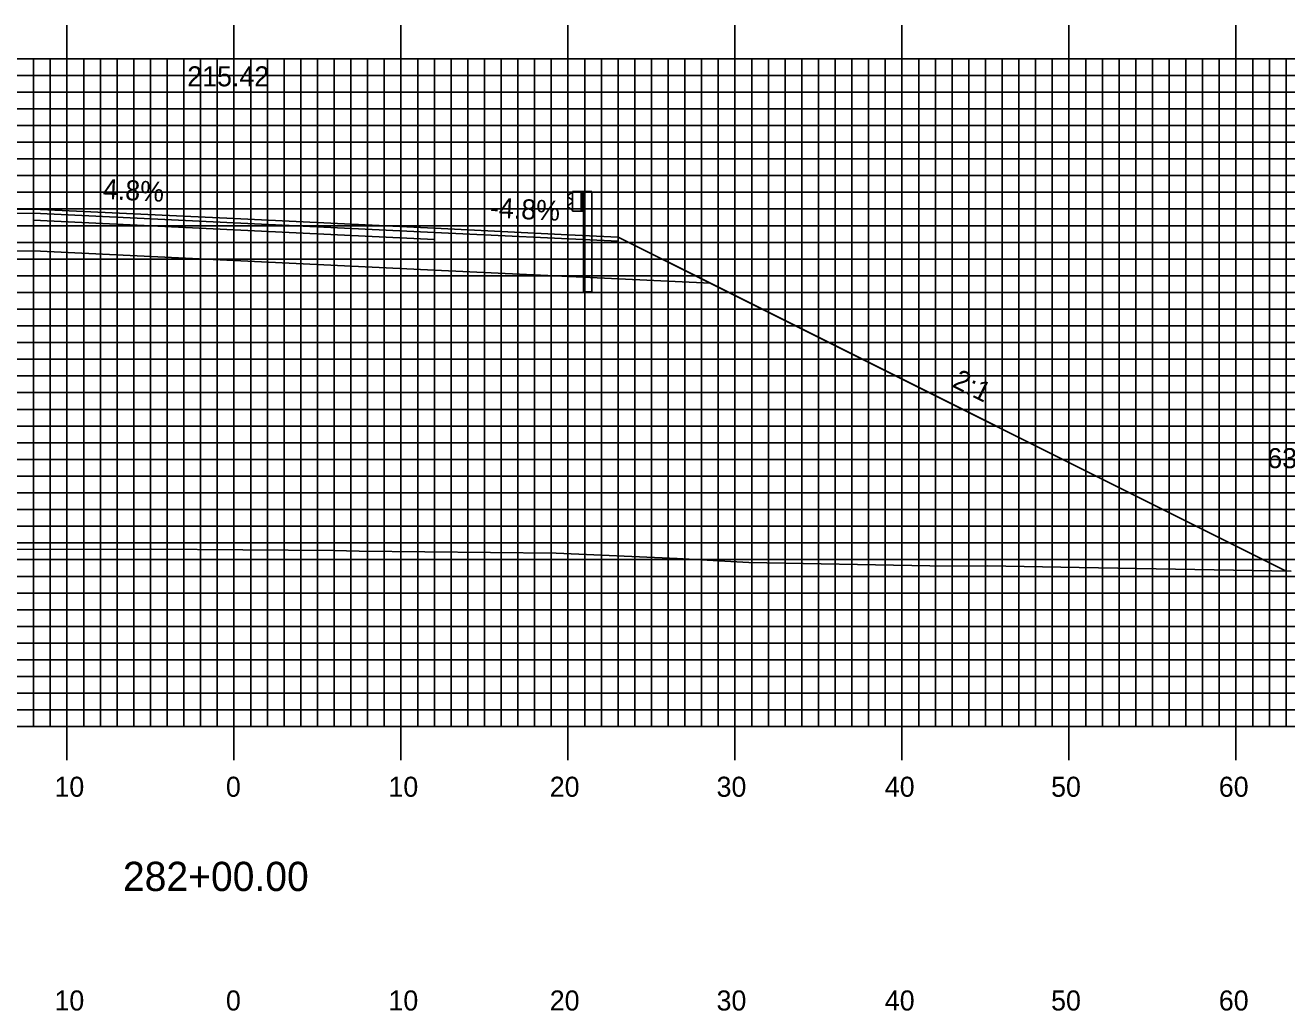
# Model space of a CAD drawing. Extents: x 1811374 to 1811717, y 442591 to 442811.
# Drawn here: x 1811526.9 to 1811602.4, y 442651.6 to 442710.7 of the extents above; entities that cross this region are included whole.
import ezdxf

# ---------------------------------------------------------------- set-up
doc = ezdxf.new("R2010")
doc.units = 0
for name, color, linetype in [('ANNOTATION', 7, 'Continuous'), ('D_Guardrail_Beam_Rt', 7, 'Continuous'), ('D_Roadway_Centerline', 7, 'Continuous'), ('D_Roadway_Centerline_Text', 7, 'Continuous'), ('D_Roadway_Edge_Shoulder', 7, 'Continuous'), ('D_Roadway_Edge_TW', 7, 'Continuous'), ('D_Roadway_Pavement', 7, 'Continuous'), ('D_Roadway_SlopeLines', 7, 'Continuous'), ('D_Roadway_SubGrade', 7, 'Continuous'), ('D_Text_Standard', 7, 'Continuous'), ('H_V ANNOTATION', 7, 'Continuous'), ('MAJOR', 7, 'Continuous'), ('MINOR', 7, 'Continuous'), ('S_Roadway_Centerline', 7, 'Continuous')]:
    doc.layers.add(name, color=color, linetype=linetype)

msp = doc.modelspace()

# ---------------------------------------------------------------- linework, layer by layer
at = {"layer": 'D_Guardrail_Beam_Rt'}
for p, q in [((1811559.674, 442700.709), (1811560.361, 442700.709)), ((1811559.674, 442699.543), (1811559.674, 442700.709)), ((1811560.194, 442700.709), (1811560.194, 442699.543)), ((1811560.299, 442700.709), (1811560.299, 442699.543)), ((1811560.361, 442700.709), (1811560.832, 442700.709)), ((1811560.361, 442700.709), (1811560.361, 442699.543)), ((1811560.832, 442700.709), (1811560.832, 442694.709)), ((1811559.584, 442700.605), (1811559.44, 442700.505)), ((1811559.44, 442700.362), (1811559.636, 442700.226)), ((1811559.636, 442700.027), (1811559.44, 442699.89)), ((1811559.674, 442700.626), (1811559.599, 442700.611)), ((1811559.669, 442700.161), (1811559.669, 442700.091)), ((1811559.44, 442699.747), (1811559.584, 442699.647)), ((1811559.599, 442699.641), (1811559.674, 442699.626)), ((1811560.361, 442699.543), (1811559.674, 442699.543)), ((1811560.34, 442694.709), (1811560.34, 442699.543)), ((1811560.34, 442694.709), (1811560.832, 442694.709))]:
    msp.add_line(p, q, dxfattribs=at)
for centre, major_axis, start_param, end_param in [((1811559.49, 442700.433), (-0.0877, 0), 5.323254, 7.243116), ((1811559.608, 442700.571), (-0.0417, 0), 4.907132, 5.323254), ((1811559.59, 442700.161), (0.0789, 0), 0, 0.959931), ((1811559.59, 442700.091), (0.0789, 0), 5.323254, 6.283185), ((1811559.49, 442699.819), (-0.0877, 0), 5.323254, 7.243116), ((1811559.608, 442699.681), (-0.0417, 0), 0.959931, 1.376053)]:
    msp.add_ellipse(centre, major_axis=major_axis, ratio=0.995501, start_param=start_param, end_param=end_param, dxfattribs=at)
at = {"layer": 'D_Roadway_Centerline'}
msp.add_lwpolyline([(1811475.943, 442679.212), (1811511.194, 442696.838), (1811516.403, 442699.442), (1811519.403, 442699.502), (1811527.403, 442699.662), (1811539.403, 442699.086), (1811551.403, 442698.51), (1811559.403, 442698.126), (1811562.403, 442697.982), (1811567.934, 442695.217), (1811602.417, 442677.975)], dxfattribs=at)
at = {"layer": 'D_Roadway_Edge_Shoulder'}
for points in [[(1811527.403, 442699.662), (1811519.403, 442699.502), (1811519.403, 442699.502), (1811516.403, 442699.442), (1811516.403, 442699.192), (1811527.403, 442699.412)], [(1811551.403, 442698.51), (1811559.403, 442698.126), (1811559.403, 442698.126), (1811562.403, 442697.982), (1811562.403, 442697.732), (1811551.403, 442698.26)]]:
    msp.add_lwpolyline(points, close=True, dxfattribs=at)
at = {"layer": 'D_Roadway_Edge_TW'}
msp.add_lwpolyline([(1811527.403, 442699.412), (1811527.403, 442699.662), (1811539.403, 442699.086), (1811551.403, 442698.51), (1811551.403, 442698.26), (1811539.403, 442698.836)], close=True, dxfattribs=at)
at = {"layer": 'D_Roadway_Pavement'}
msp.add_lwpolyline([(1811527.403, 442698.995), (1811527.403, 442699.412), (1811539.403, 442698.836), (1811551.403, 442698.26), (1811551.403, 442697.843), (1811539.403, 442698.419)], close=True, dxfattribs=at)
for points in [[(1811527.403, 442699.412), (1811527.403, 442698.995)], [(1811551.403, 442698.26), (1811551.403, 442697.843)]]:
    msp.add_lwpolyline(points, dxfattribs=at)
at = {"layer": 'D_Roadway_SlopeLines'}
msp.add_lwpolyline([(1811562.403, 442697.982), (1811602.417, 442677.975)], dxfattribs=at)
at = {"layer": 'D_Roadway_SubGrade'}
for points in [[(1811527.403, 442698.995), (1811527.403, 442699.412), (1811516.403, 442699.192), (1811516.403, 442699.442), (1811511.194, 442696.838), (1811527.403, 442697.162)], [(1811527.403, 442697.162), (1811527.403, 442699.412), (1811527.403, 442698.995), (1811539.403, 442698.419), (1811551.403, 442697.843), (1811551.403, 442698.26), (1811551.403, 442696.01), (1811539.403, 442696.586)], [(1811551.403, 442697.843), (1811551.403, 442698.26), (1811562.403, 442697.732), (1811562.403, 442697.982), (1811567.934, 442695.217), (1811551.403, 442696.01)]]:
    msp.add_lwpolyline(points, close=True, dxfattribs=at)
at = {"layer": 'MAJOR'}
for p, q in [((1811529.403, 442710.669), (1811529.403, 442708.665)), ((1811539.403, 442710.669), (1811539.403, 442708.665)), ((1811549.403, 442710.669), (1811549.403, 442708.665)), ((1811559.403, 442710.669), (1811559.403, 442708.665)), ((1811569.403, 442710.669), (1811569.403, 442708.665)), ((1811579.403, 442710.669), (1811579.403, 442708.665)), ((1811589.403, 442710.669), (1811589.403, 442708.665)), ((1811599.403, 442710.669), (1811599.403, 442708.665)), ((1811399.403, 442708.665), (1811679.403, 442708.665)), ((1811399.403, 442708.665), (1811679.403, 442708.665)), ((1811529.403, 442668.665), (1811529.403, 442708.665)), ((1811539.403, 442668.665), (1811539.403, 442708.665)), ((1811549.403, 442668.665), (1811549.403, 442708.665)), ((1811559.403, 442668.665), (1811559.403, 442708.665)), ((1811569.403, 442668.665), (1811569.403, 442708.665)), ((1811579.403, 442668.665), (1811579.403, 442708.665)), ((1811589.403, 442668.665), (1811589.403, 442708.665)), ((1811599.403, 442668.665), (1811599.403, 442708.665)), ((1811399.403, 442703.665), (1811679.403, 442703.665)), ((1811399.403, 442698.665), (1811679.403, 442698.665)), ((1811399.403, 442693.665), (1811679.403, 442693.665)), ((1811399.403, 442688.665), (1811679.403, 442688.665)), ((1811399.403, 442683.665), (1811679.403, 442683.665)), ((1811399.403, 442678.665), (1811679.403, 442678.665)), ((1811399.403, 442673.665), (1811679.403, 442673.665)), ((1811399.403, 442668.665), (1811679.403, 442668.665)), ((1811399.403, 442668.665), (1811679.403, 442668.665)), ((1811529.403, 442666.661), (1811529.403, 442668.665)), ((1811539.403, 442666.661), (1811539.403, 442668.665)), ((1811549.403, 442666.661), (1811549.403, 442668.665)), ((1811559.403, 442666.661), (1811559.403, 442668.665)), ((1811569.403, 442666.661), (1811569.403, 442668.665)), ((1811579.403, 442666.661), (1811579.403, 442668.665)), ((1811589.403, 442666.661), (1811589.403, 442668.665)), ((1811599.403, 442666.661), (1811599.403, 442668.665))]:
    msp.add_line(p, q, dxfattribs=at)
at = {"layer": 'MINOR'}
for p, q in [((1811527.403, 442668.665), (1811527.403, 442708.665)), ((1811528.403, 442668.665), (1811528.403, 442708.665)), ((1811530.403, 442668.665), (1811530.403, 442708.665)), ((1811531.403, 442668.665), (1811531.403, 442708.665)), ((1811532.403, 442668.665), (1811532.403, 442708.665)), ((1811533.403, 442668.665), (1811533.403, 442708.665)), ((1811534.403, 442668.665), (1811534.403, 442708.665)), ((1811535.403, 442668.665), (1811535.403, 442708.665)), ((1811536.403, 442668.665), (1811536.403, 442708.665)), ((1811537.403, 442668.665), (1811537.403, 442708.665)), ((1811538.403, 442668.665), (1811538.403, 442708.665)), ((1811540.403, 442668.665), (1811540.403, 442708.665)), ((1811541.403, 442668.665), (1811541.403, 442708.665)), ((1811542.403, 442668.665), (1811542.403, 442708.665)), ((1811543.403, 442668.665), (1811543.403, 442708.665)), ((1811544.403, 442668.665), (1811544.403, 442708.665)), ((1811545.403, 442668.665), (1811545.403, 442708.665)), ((1811546.403, 442668.665), (1811546.403, 442708.665)), ((1811547.403, 442668.665), (1811547.403, 442708.665)), ((1811548.403, 442668.665), (1811548.403, 442708.665)), ((1811550.403, 442668.665), (1811550.403, 442708.665)), ((1811551.403, 442668.665), (1811551.403, 442708.665)), ((1811552.403, 442668.665), (1811552.403, 442708.665)), ((1811553.403, 442668.665), (1811553.403, 442708.665)), ((1811554.403, 442668.665), (1811554.403, 442708.665)), ((1811555.403, 442668.665), (1811555.403, 442708.665)), ((1811556.403, 442668.665), (1811556.403, 442708.665)), ((1811557.403, 442668.665), (1811557.403, 442708.665)), ((1811558.403, 442668.665), (1811558.403, 442708.665)), ((1811560.403, 442668.665), (1811560.403, 442708.665)), ((1811561.403, 442668.665), (1811561.403, 442708.665)), ((1811562.403, 442668.665), (1811562.403, 442708.665)), ((1811563.403, 442668.665), (1811563.403, 442708.665)), ((1811564.403, 442668.665), (1811564.403, 442708.665)), ((1811565.403, 442668.665), (1811565.403, 442708.665)), ((1811566.403, 442668.665), (1811566.403, 442708.665)), ((1811567.403, 442668.665), (1811567.403, 442708.665)), ((1811568.403, 442668.665), (1811568.403, 442708.665)), ((1811570.403, 442668.665), (1811570.403, 442708.665)), ((1811571.403, 442668.665), (1811571.403, 442708.665)), ((1811572.403, 442668.665), (1811572.403, 442708.665)), ((1811573.403, 442668.665), (1811573.403, 442708.665)), ((1811574.403, 442668.665), (1811574.403, 442708.665)), ((1811575.403, 442668.665), (1811575.403, 442708.665)), ((1811576.403, 442668.665), (1811576.403, 442708.665)), ((1811577.403, 442668.665), (1811577.403, 442708.665)), ((1811578.403, 442668.665), (1811578.403, 442708.665)), ((1811580.403, 442668.665), (1811580.403, 442708.665)), ((1811581.403, 442668.665), (1811581.403, 442708.665)), ((1811582.403, 442668.665), (1811582.403, 442708.665)), ((1811583.403, 442668.665), (1811583.403, 442708.665)), ((1811584.403, 442668.665), (1811584.403, 442708.665)), ((1811585.403, 442668.665), (1811585.403, 442708.665)), ((1811586.403, 442668.665), (1811586.403, 442708.665)), ((1811587.403, 442668.665), (1811587.403, 442708.665)), ((1811588.403, 442668.665), (1811588.403, 442708.665)), ((1811590.403, 442668.665), (1811590.403, 442708.665)), ((1811591.403, 442668.665), (1811591.403, 442708.665)), ((1811592.403, 442668.665), (1811592.403, 442708.665)), ((1811593.403, 442668.665), (1811593.403, 442708.665)), ((1811594.403, 442668.665), (1811594.403, 442708.665)), ((1811595.403, 442668.665), (1811595.403, 442708.665)), ((1811596.403, 442668.665), (1811596.403, 442708.665)), ((1811597.403, 442668.665), (1811597.403, 442708.665)), ((1811598.403, 442668.665), (1811598.403, 442708.665)), ((1811600.403, 442668.665), (1811600.403, 442708.665)), ((1811601.403, 442668.665), (1811601.403, 442708.665)), ((1811602.403, 442668.665), (1811602.403, 442708.665)), ((1811399.403, 442707.665), (1811679.403, 442707.665)), ((1811399.403, 442706.665), (1811679.403, 442706.665)), ((1811399.403, 442705.665), (1811679.403, 442705.665)), ((1811399.403, 442704.665), (1811679.403, 442704.665)), ((1811399.403, 442702.665), (1811679.403, 442702.665)), ((1811399.403, 442701.665), (1811679.403, 442701.665)), ((1811399.403, 442700.665), (1811679.403, 442700.665)), ((1811399.403, 442699.665), (1811679.403, 442699.665)), ((1811399.403, 442697.665), (1811679.403, 442697.665)), ((1811399.403, 442696.665), (1811679.403, 442696.665)), ((1811399.403, 442695.665), (1811679.403, 442695.665)), ((1811399.403, 442694.665), (1811679.403, 442694.665)), ((1811399.403, 442692.665), (1811679.403, 442692.665)), ((1811399.403, 442691.665), (1811679.403, 442691.665)), ((1811399.403, 442690.665), (1811679.403, 442690.665)), ((1811399.403, 442689.665), (1811679.403, 442689.665)), ((1811399.403, 442687.665), (1811679.403, 442687.665)), ((1811399.403, 442686.665), (1811679.403, 442686.665)), ((1811399.403, 442685.665), (1811679.403, 442685.665)), ((1811399.403, 442684.665), (1811679.403, 442684.665)), ((1811399.403, 442682.665), (1811679.403, 442682.665)), ((1811399.403, 442681.665), (1811679.403, 442681.665)), ((1811399.403, 442680.665), (1811679.403, 442680.665)), ((1811399.403, 442679.665), (1811679.403, 442679.665)), ((1811399.403, 442677.665), (1811679.403, 442677.665)), ((1811399.403, 442676.665), (1811679.403, 442676.665)), ((1811399.403, 442675.665), (1811679.403, 442675.665)), ((1811399.403, 442674.665), (1811679.403, 442674.665)), ((1811399.403, 442672.665), (1811679.403, 442672.665)), ((1811399.403, 442671.665), (1811679.403, 442671.665)), ((1811399.403, 442670.665), (1811679.403, 442670.665)), ((1811399.403, 442669.665), (1811679.403, 442669.665))]:
    msp.add_line(p, q, dxfattribs=at)
at = {"layer": 'S_Roadway_Centerline'}
msp.add_lwpolyline([(1811451.547, 442679.343), (1811469.833, 442679.364), (1811482.486, 442679.05), (1811485.617, 442679.003), (1811487.37, 442678.979), (1811496.912, 442679.116), (1811507.938, 442679.324), (1811509.947, 442679.355), (1811513.992, 442679.282), (1811534.488, 442679.3), (1811545.389, 442679.213), (1811546.894, 442679.176), (1811558.697, 442679.052), (1811565.946, 442678.734), (1811570.239, 442678.492), (1811581.066, 442678.294), (1811583.435, 442678.275), (1811584.52, 442678.298), (1811590.009, 442678.192), (1811602.715, 442677.97)], dxfattribs=at)

# ---------------------------------------------------------------- texts
at = {"layer": 'ANNOTATION'}
for s, rotation, p in [('4.8%', 357.25191, (1811531.532, 442700.266)), ('-4.8%', 357.25191, (1811554.711, 442699.154)), ('2:1', 333.43495, (1811582.344, 442689.048))]:
    msp.add_text(s, height=1.2, rotation=rotation, dxfattribs=at).set_placement(p)
at = {"layer": 'D_Roadway_Centerline'}
for s, p in [('C', (1811539.398, 442699.086)), ('L', (1811539.403, 442699.079))]:
    msp.add_text(s, height=0.0146, dxfattribs=at).set_placement(p)
at = {"layer": 'D_Roadway_Centerline_Text'}
msp.add_text('215.42', height=1.2, dxfattribs=at).set_placement((1811536.604, 442707.009))
at = {"layer": 'D_Text_Standard'}
msp.add_text("63.0'", height=1.2, dxfattribs=at).set_placement((1811601.277, 442684.142))
at = {"layer": 'H_V ANNOTATION'}
for s, height, p in [('10', 1.2, (1811528.653, 442664.465)), ('0', 1.2, (1811538.921, 442664.465)), ('10', 1.2, (1811548.653, 442664.465)), ('20', 1.2, (1811558.311, 442664.465)), ('30', 1.2, (1811568.3, 442664.465)), ('40', 1.2, (1811578.375, 442664.465)), ('50', 1.2, (1811588.332, 442664.465)), ('60', 1.2, (1811598.375, 442664.465)), ('282+00.00', 1.75, (1811532.754, 442658.821)), ('10', 1.2, (1811528.653, 442651.665)), ('0', 1.2, (1811538.921, 442651.665)), ('10', 1.2, (1811548.653, 442651.665)), ('20', 1.2, (1811558.311, 442651.665)), ('30', 1.2, (1811568.3, 442651.665)), ('40', 1.2, (1811578.375, 442651.665)), ('50', 1.2, (1811588.332, 442651.665)), ('60', 1.2, (1811598.375, 442651.665))]:
    msp.add_text(s, height=height, dxfattribs=at).set_placement(p)

doc.saveas('drawing.dxf')
